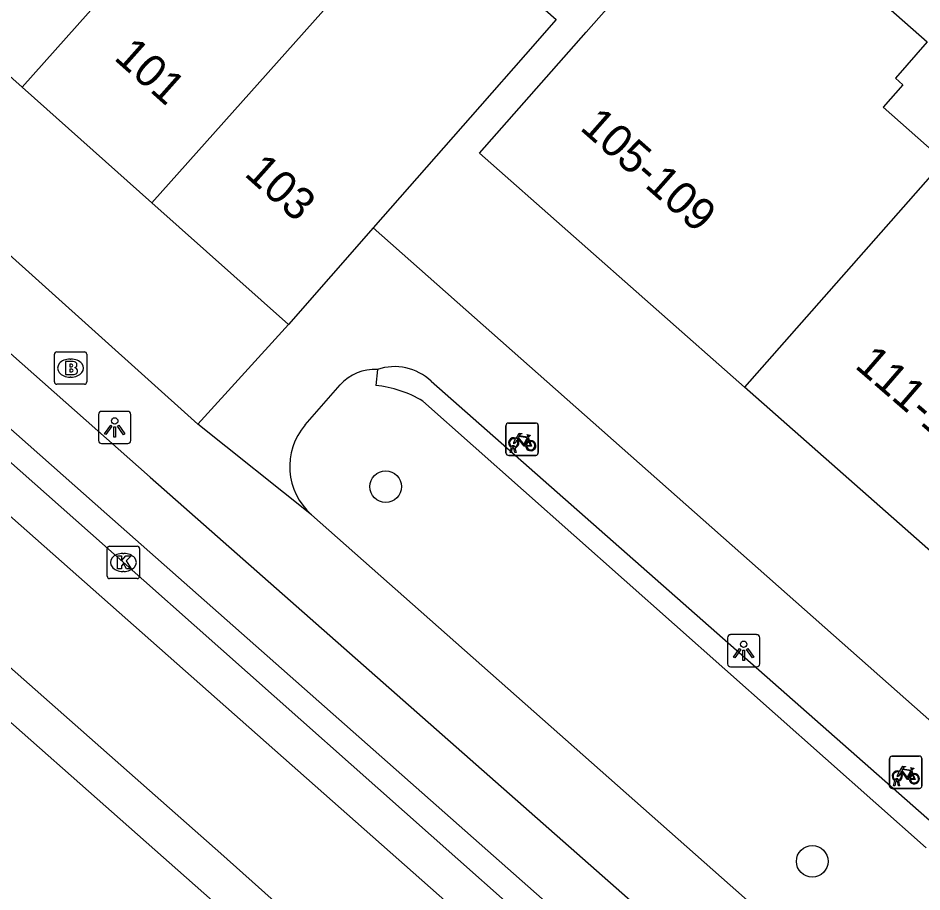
# Model space of a CAD drawing. Extents: x 162074 to 163034, y 381824 to 382557.
# Drawn here: x 162622.35 to 162650.31, y 382193.36 to 382220.39 of the extents above; entities that cross this region are included whole.
import ezdxf

# ---------------------------------------------------------------- set-up
doc = ezdxf.new("R2010")
doc.units = 0
for name, color, linetype in [('IMGEO_Boom', 7, 'Continuous'), ('IMGEO_Brandkraan', 7, 'Continuous'), ('IMGEO_Fietsenrek', 7, 'Continuous'), ('IMGEO_Fietspad_gesloten', 7, 'Continuous'), ('IMGEO_Haag', 7, 'Continuous'), ('IMGEO_Kolk', 7, 'Continuous'), ('IMGEO_Lichtpunt', 7, 'Continuous'), ('IMGEO_Pand', 7, 'Continuous'), ('IMGEO_Pand_nummerreeks', 7, 'Continuous'), ('IMGEO_Rijbaan_lokaal_open', 7, 'Continuous'), ('IMGEO_Voetpad_open', 7, 'Continuous')]:
    doc.layers.add(name, color=color, linetype=linetype)

msp = doc.modelspace()

# ---------------------------------------------------------------- linework, layer by layer
at = {"layer": 'IMGEO_Boom'}
for centre in [(162633.721, 382205.893), (162646.915, 382194.303)]:
    msp.add_circle(centre, 0.489, dxfattribs=at)
at = {"layer": 'IMGEO_Brandkraan'}
for p, q in [((162623.546, 382210.06), (162624.398, 382210.06)), ((162623.471, 382209.134), (162623.471, 382209.986)), ((162623.959, 382209.84), (162623.984, 382209.84)), ((162624.472, 382209.986), (162624.472, 382209.134)), ((162623.982, 382209.28), (162623.957, 382209.28)), ((162624.398, 382209.06), (162623.546, 382209.06))]:
    msp.add_line(p, q, dxfattribs=at)
for points in [[(162623.546, 382210.06), (162624.398, 382210.06)], [(162623.471, 382209.134), (162623.471, 382209.986)], [(162623.819, 382209.76), (162623.819, 382209.36), (162624.032, 382209.36)], [(162624.05, 382209.76), (162623.819, 382209.76)], [(162624.472, 382209.986), (162624.472, 382209.134)], [(162623.998, 382209.679), (162623.944, 382209.679), (162623.944, 382209.603)], [(162623.944, 382209.603), (162623.997, 382209.603)], [(162624.006, 382209.527), (162623.944, 382209.527), (162623.944, 382209.446)], [(162623.944, 382209.446), (162624.006, 382209.446)], [(162624.398, 382209.06), (162623.546, 382209.06)]]:
    msp.add_lwpolyline(points, dxfattribs=at)
for centre, radius, start, end in [((162623.548, 382209.984), 0.0765, 91.552, 178.448), ((162623.548, 382209.984), 0.0765, 91.552, 178.448), ((162624.396, 382209.984), 0.0765, 1.552, 88.448), ((162624.396, 382209.984), 0.0765, 1.552, 88.448), ((162624.054, 382209.615), 0.145, 59.4692, 91.5367), ((162623.999, 382209.641), 0.0379, 267.8285, 90.9355), ((162624.007, 382209.486), 0.0404, 269.8759, 90.5077), ((162624.079, 382209.662), 0.0922, 285.5137, 58.1501), ((162624.084, 382209.47), 0.105, 301.3115, 78.989), ((162624.038, 382209.611), 0.251, 268.6676, 293.5347), ((162623.548, 382209.136), 0.0765, 181.552, 268.448), ((162623.548, 382209.136), 0.0765, 181.552, 268.448), ((162624.396, 382209.136), 0.0765, 271.552, 358.448), ((162624.396, 382209.136), 0.0765, 271.552, 358.448)]:
    msp.add_arc(centre, radius, start, end, dxfattribs=at)
for centre, major_axis, ratio, start_param, end_param in [((162623.958, 382209.56), (-0.387, 0.002), 0.722429, 4.712389, 7.853982), ((162623.983, 382209.56), (-0.39, 0.002), 0.717154, 1.570796, 4.712389)]:
    msp.add_ellipse(centre, major_axis=major_axis, ratio=ratio, start_param=start_param, end_param=end_param, dxfattribs=at)
at = {"layer": 'IMGEO_Fietsenrek'}
for p, q in [((162637.516, 382207.861), (162638.357, 382207.861)), ((162638.357, 382207.861), (162637.516, 382207.861)), ((162637.441, 382206.936), (162637.441, 382207.777)), ((162637.441, 382207.777), (162637.441, 382206.936)), ((162638.441, 382207.786), (162638.441, 382206.945)), ((162638.441, 382206.945), (162638.441, 382207.786)), ((162638.128, 382207.41), (162638.164, 382207.315)), ((162637.568, 382206.945), (162637.607, 382207.105)), ((162637.637, 382207.093), (162637.602, 382206.945)), ((162637.679, 382207.117), (162637.678, 382207.121)), ((162637.72, 382206.945), (162637.686, 382207.087)), ((162637.71, 382207.128), (162637.711, 382207.121)), ((162637.718, 382207.091), (162637.753, 382206.945)), ((162638.366, 382206.861), (162637.525, 382206.861)), ((162637.525, 382206.861), (162638.366, 382206.861)), ((162637.602, 382206.945), (162637.568, 382206.945)), ((162637.753, 382206.945), (162637.72, 382206.945)), ((162649.307, 382196.633), (162649.307, 382197.474)), ((162649.307, 382197.474), (162649.307, 382196.633)), ((162649.382, 382197.558), (162650.223, 382197.558)), ((162650.223, 382197.558), (162649.382, 382197.558)), ((162650.307, 382197.483), (162650.307, 382196.642)), ((162650.307, 382196.642), (162650.307, 382197.483)), ((162649.994, 382197.107), (162650.03, 382197.012)), ((162649.434, 382196.642), (162649.473, 382196.802)), ((162649.468, 382196.642), (162649.434, 382196.642)), ((162649.503, 382196.79), (162649.468, 382196.642)), ((162649.545, 382196.814), (162649.544, 382196.818)), ((162649.586, 382196.642), (162649.552, 382196.784)), ((162649.576, 382196.825), (162649.577, 382196.818)), ((162649.584, 382196.788), (162649.619, 382196.642)), ((162649.619, 382196.642), (162649.586, 382196.642)), ((162650.232, 382196.558), (162649.391, 382196.558)), ((162649.391, 382196.558), (162650.232, 382196.558))]:
    msp.add_line(p, q, dxfattribs=at)
for points in [[(162637.754, 382207.387), (162637.849, 382207.551), (162637.935, 382207.537), (162637.937, 382207.528), (162637.881, 382207.517), (162637.854, 382207.472), (162638.11, 382207.431)], [(162637.775, 382207.335), (162637.723, 382207.245), (162637.683, 382207.22), (162637.684, 382207.267), (162637.739, 382207.361)], [(162638.05, 382207.143), (162638, 382207.143), (162637.809, 382207.394), (162637.79, 382207.362)], [(162638.097, 382207.406), (162637.84, 382207.447), (162637.823, 382207.418), (162637.99, 382207.198), (162638.097, 382207.406)], [(162638.145, 382207.308), (162638.115, 382207.385), (162638.006, 382207.167), (162638.049, 382207.167)], [(162638.079, 382207.167), (162638.199, 382207.166), (162638.155, 382207.28)], [(162638.175, 382207.287), (162638.23, 382207.142), (162638.08, 382207.142)], [(162638.11, 382207.431), (162638.135, 382207.48), (162638.129, 382207.484), (162638.106, 382207.488), (162638.094, 382207.495), (162638.093, 382207.498), (162638.095, 382207.503), (162638.19, 382207.488), (162638.192, 382207.478), (162638.182, 382207.465), (162638.17, 382207.459), (162638.156, 382207.465), (162638.128, 382207.41)], [(162649.62, 382197.084), (162649.715, 382197.248), (162649.801, 382197.234), (162649.803, 382197.225), (162649.747, 382197.214), (162649.72, 382197.169), (162649.976, 382197.128)], [(162649.976, 382197.128), (162650.001, 382197.177), (162649.995, 382197.181), (162649.972, 382197.185), (162649.96, 382197.192), (162649.959, 382197.195), (162649.961, 382197.2), (162650.056, 382197.185), (162650.058, 382197.175), (162650.048, 382197.162), (162650.036, 382197.156), (162650.022, 382197.162), (162649.994, 382197.107)], [(162649.641, 382197.032), (162649.589, 382196.942), (162649.549, 382196.917), (162649.55, 382196.964), (162649.605, 382197.058)], [(162649.916, 382196.84), (162649.866, 382196.84), (162649.675, 382197.091), (162649.656, 382197.059)], [(162649.963, 382197.103), (162649.706, 382197.144), (162649.689, 382197.115), (162649.856, 382196.895), (162649.963, 382197.103)], [(162650.011, 382197.005), (162649.981, 382197.082), (162649.872, 382196.864), (162649.915, 382196.864)], [(162649.945, 382196.864), (162650.065, 382196.863), (162650.021, 382196.977)], [(162650.041, 382196.984), (162650.096, 382196.839), (162649.946, 382196.839)]]:
    msp.add_lwpolyline(points, dxfattribs=at)
for centre, radius, start, end in [((162637.519, 382207.783), 0.0779, 92.4484, 184.2845), ((162637.519, 382207.783), 0.0779, 92.4484, 184.2845), ((162638.363, 382207.783), 0.0779, 2.4484, 94.2845), ((162638.363, 382207.783), 0.0779, 2.4484, 94.2845), ((162637.681, 382207.246), 0.159, 62.6766, 242.1369), ((162637.681, 382207.246), 0.129, 63.3192, 238.903), ((162637.681, 382207.246), 0.129, 283.6043, 43.4302), ((162637.681, 382207.246), 0.159, 283.5766, 46.6042), ((162638.208, 382207.162), 0.159, 113.3408, 178.3217), ((162638.208, 382207.162), 0.159, 187.0065, 105.7708), ((162638.208, 382207.162), 0.129, 113.923, 177.9556), ((162638.208, 382207.162), 0.129, 188.6715, 104.5883), ((162637.661, 382207.117), 0.0499, 12.8025, 158.6934), ((162637.681, 382207.246), 0.159, 253.9967, 271.7867), ((162637.661, 382207.117), 0.0174, 12.8025, 163.4502), ((162637.681, 382207.246), 0.129, 253.415, 269.0204), ((162637.519, 382206.939), 0.0779, 182.4484, 274.2845), ((162637.519, 382206.939), 0.0779, 182.4484, 274.2845), ((162638.363, 382206.939), 0.0779, 272.4484, 4.2845), ((162638.363, 382206.939), 0.0779, 272.4484, 4.2845), ((162649.385, 382197.48), 0.0779, 92.4484, 184.2845), ((162649.385, 382197.48), 0.0779, 92.4484, 184.2845), ((162650.229, 382197.48), 0.0779, 2.4484, 94.2845), ((162650.229, 382197.48), 0.0779, 2.4484, 94.2845), ((162649.547, 382196.943), 0.159, 62.6766, 242.1369), ((162649.547, 382196.943), 0.129, 63.3192, 238.903), ((162649.547, 382196.943), 0.129, 283.6043, 43.4302), ((162649.547, 382196.943), 0.159, 283.5766, 46.6042), ((162650.074, 382196.859), 0.159, 113.3408, 178.3217), ((162650.074, 382196.859), 0.159, 187.0065, 105.7708), ((162650.074, 382196.859), 0.129, 113.923, 177.9556), ((162650.074, 382196.859), 0.129, 188.6715, 104.5883), ((162649.385, 382196.636), 0.0779, 182.4484, 274.2845), ((162649.385, 382196.636), 0.0779, 182.4484, 274.2845), ((162649.527, 382196.814), 0.0499, 12.8025, 158.6934), ((162649.547, 382196.943), 0.159, 253.9967, 271.7867), ((162649.527, 382196.814), 0.0174, 12.8025, 163.4502), ((162649.547, 382196.943), 0.129, 253.415, 269.0204), ((162650.229, 382196.636), 0.0779, 272.4484, 4.2845), ((162650.229, 382196.636), 0.0779, 272.4484, 4.2845)]:
    msp.add_arc(centre, radius, start, end, dxfattribs=at)
at = {"layer": 'IMGEO_Fietspad_gesloten'}
for points in [[(162640.048, 382182.752), (162606.944, 382212.014), (162601.77, 382216.788)], [(162644.019, 382187.212), (162624.584, 382204.454), (162610.981, 382216.511)]]:
    msp.add_lwpolyline(points, dxfattribs=at)
at = {"layer": 'IMGEO_Haag'}
for points in [[(162633.463, 382209.519), (162633.412, 382209.021)], [(162634.868, 382208.539), (162650.441, 382194.719)]]:
    msp.add_lwpolyline(points, dxfattribs=at)
msp.add_arc((162633.055, 382205.502), 3.538, 59.1635, 84.2029, dxfattribs=at)
at = {"layer": 'IMGEO_Kolk'}
for p, q in [((162625.104, 382203.123), (162625.104, 382203.975)), ((162625.179, 382204.049), (162626.031, 382204.049)), ((162626.105, 382203.975), (162626.105, 382203.123)), ((162625.592, 382203.829), (162625.617, 382203.829)), ((162626.031, 382203.049), (162625.179, 382203.049)), ((162625.615, 382203.269), (162625.59, 382203.269))]:
    msp.add_line(p, q, dxfattribs=at)
for points in [[(162625.104, 382203.123), (162625.104, 382203.975)], [(162625.179, 382204.049), (162626.031, 382204.049)], [(162626.105, 382203.975), (162626.105, 382203.123)], [(162625.425, 382203.749), (162625.548, 382203.749), (162625.548, 382203.598), (162625.678, 382203.749), (162625.842, 382203.749), (162625.696, 382203.598), (162625.849, 382203.349), (162625.697, 382203.349), (162625.612, 382203.513), (162625.548, 382203.446), (162625.548, 382203.349), (162625.425, 382203.349), (162625.425, 382203.749)], [(162626.031, 382203.049), (162625.179, 382203.049)]]:
    msp.add_lwpolyline(points, dxfattribs=at)
for centre, start, end in [((162625.181, 382203.973), 91.552, 178.448), ((162625.181, 382203.973), 91.552, 178.448), ((162626.029, 382203.973), 1.552, 88.448), ((162626.029, 382203.973), 1.552, 88.448), ((162625.181, 382203.125), 181.552, 268.448), ((162625.181, 382203.125), 181.552, 268.448), ((162626.029, 382203.125), 271.552, 358.448), ((162626.029, 382203.125), 271.552, 358.448)]:
    msp.add_arc(centre, 0.0765, start, end, dxfattribs=at)
for centre, major_axis, ratio, start_param, end_param in [((162625.591, 382203.549), (-0.387, 0.002), 0.722429, 4.712389, 7.853982), ((162625.616, 382203.549), (-0.39, 0.002), 0.717154, 1.570796, 4.712389)]:
    msp.add_ellipse(centre, major_axis=major_axis, ratio=ratio, start_param=start_param, end_param=end_param, dxfattribs=at)
at = {"layer": 'IMGEO_Lichtpunt'}
for p, q in [((162624.838, 382208.127), (162624.838, 382207.32)), ((162624.838, 382208.127), (162624.838, 382207.32)), ((162625.74, 382208.222), (162624.932, 382208.222)), ((162625.74, 382208.222), (162624.932, 382208.222)), ((162625.834, 382207.32), (162625.834, 382208.127)), ((162625.834, 382207.32), (162625.834, 382208.127)), ((162624.932, 382207.226), (162625.74, 382207.226)), ((162624.932, 382207.226), (162625.74, 382207.226)), ((162644.294, 382201.22), (162644.294, 382200.413)), ((162644.294, 382201.22), (162644.294, 382200.413)), ((162645.196, 382201.315), (162644.388, 382201.315)), ((162645.196, 382201.315), (162644.388, 382201.315)), ((162645.29, 382200.413), (162645.29, 382201.22)), ((162645.29, 382200.413), (162645.29, 382201.22)), ((162644.388, 382200.319), (162645.196, 382200.319)), ((162644.388, 382200.319), (162645.196, 382200.319))]:
    msp.add_line(p, q, dxfattribs=at)
for points in [[(162625.212, 382207.791), (162625.251, 382207.763), (162625.063, 382207.501), (162625.025, 382207.528), (162625.212, 382207.791)], [(162625.314, 382207.743), (162625.361, 382207.743), (162625.361, 382207.421), (162625.314, 382207.421), (162625.314, 382207.743)], [(162625.424, 382207.763), (162625.462, 382207.79), (162625.649, 382207.528), (162625.61, 382207.5), (162625.424, 382207.763)], [(162644.668, 382200.884), (162644.707, 382200.856), (162644.519, 382200.594), (162644.481, 382200.621), (162644.668, 382200.884)], [(162644.77, 382200.836), (162644.817, 382200.836), (162644.817, 382200.514), (162644.77, 382200.514), (162644.77, 382200.836)], [(162644.88, 382200.856), (162644.918, 382200.883), (162645.105, 382200.621), (162645.066, 382200.593), (162644.88, 382200.856)]]:
    msp.add_lwpolyline(points, dxfattribs=at)
for centre in [(162625.337, 382207.925), (162644.793, 382201.018)]:
    msp.add_circle(centre, 0.0994, dxfattribs=at)
for centre, start, end in [((162624.932, 382208.127), 90, 180), ((162624.932, 382208.127), 90, 180), ((162625.74, 382208.127), 0, 90), ((162625.74, 382208.127), 0, 90), ((162624.932, 382207.32), 180, 270), ((162624.932, 382207.32), 180, 270), ((162625.74, 382207.32), 270, 0), ((162625.74, 382207.32), 270, 360), ((162644.388, 382201.22), 90, 180), ((162644.388, 382201.22), 90, 180), ((162645.196, 382201.22), 0, 90), ((162645.196, 382201.22), 0, 90), ((162644.388, 382200.413), 180, 270), ((162644.388, 382200.413), 180, 270), ((162645.196, 382200.413), 270, 0), ((162645.196, 382200.413), 270, 360)]:
    msp.add_arc(centre, 0.0946, start, end, dxfattribs=at)
at = {"layer": 'IMGEO_Pand'}
for points in [[(162622.476, 382218.253), (162629.366, 382225.981), (162630.765, 382227.574)], [(162626.487, 382214.676), (162632.309, 382221.207), (162634.815, 382224.018)], [(162634.815, 382224.018), (162638.997, 382220.344), (162638.043, 382219.258), (162636.635, 382217.655), (162633.334, 382213.898)], [(162644.818, 382208.974), (162636.619, 382216.203), (162639.926, 382219.954), (162642.927, 382223.357), (162643.235, 382223.086), (162643.082, 382222.912), (162644.858, 382221.346), (162645.493, 382222.066), (162645.707, 382221.878), (162646.685, 382222.988), (162650.473, 382219.648), (162649.488, 382218.531), (162649.722, 382218.325), (162649.109, 382217.63), (162650.988, 382215.973), (162650.953, 382215.934)], [(162622.476, 382218.253), (162618.996, 382221.355), (162618.298, 382221.998)], [(162626.487, 382214.676), (162622.476, 382218.253)], [(162650.953, 382215.934), (162644.818, 382208.974)], [(162630.71, 382210.912), (162626.487, 382214.676)], [(162633.334, 382213.898), (162630.71, 382210.912)], [(162653.016, 382201.746), (162644.818, 382208.974)]]:
    msp.add_lwpolyline(points, dxfattribs=at)
at = {"layer": 'IMGEO_Rijbaan_lokaal_open'}
for points in [[(162640.86, 382183.603), (162628.624, 382194.55), (162608.204, 382212.566), (162602.641, 382217.615)], [(162610.213, 382215.487), (162643.217, 382186.312)]]:
    msp.add_lwpolyline(points, dxfattribs=at)
at = {"layer": 'IMGEO_Voetpad_open'}
for points in [[(162627.91, 382207.821), (162610.896, 382223.128)], [(162614.546, 382216.706), (162613.365, 382215.409), (162625.089, 382205.044), (162658.585, 382175.454)], [(162614.546, 382216.706), (162626.433, 382206.191), (162659.783, 382176.802), (162658.585, 382175.454)], [(162633.334, 382213.898), (162692.173, 382161.844)], [(162630.71, 382210.912), (162627.91, 382207.821)], [(162631.225, 382207.802), (162632.316, 382209.037)], [(162635.127, 382209.158), (162650.889, 382195.267)], [(162631.425, 382205.025), (162627.91, 382207.821)], [(162646.961, 382191.28), (162631.425, 382205.025)]]:
    msp.add_lwpolyline(points, dxfattribs=at)
for centre, radius, start, end in [((162633.385, 382208.098), 1.423, 86.8678, 138.719), ((162633.993, 382207.945), 1.66, 46.9118, 108.6072), ((162632.738, 382206.515), 1.986, 139.625, 228.6137)]:
    msp.add_arc(centre, radius, start, end, dxfattribs=at)

# ---------------------------------------------------------------- texts
at = {"layer": 'IMGEO_Pand_nummerreeks'}
for s, rotation, p in [('101', 318.2831, (162625.282, 382219.126)), ('105-109', 318.558, (162639.696, 382216.956)), ('103', 318.2831, (162629.315, 382215.532)), ('111-115', 319.1023, (162648.2, 382209.593))]:
    msp.add_text(s, height=1, rotation=rotation, dxfattribs=at).set_placement(p)

doc.saveas('drawing.dxf')
